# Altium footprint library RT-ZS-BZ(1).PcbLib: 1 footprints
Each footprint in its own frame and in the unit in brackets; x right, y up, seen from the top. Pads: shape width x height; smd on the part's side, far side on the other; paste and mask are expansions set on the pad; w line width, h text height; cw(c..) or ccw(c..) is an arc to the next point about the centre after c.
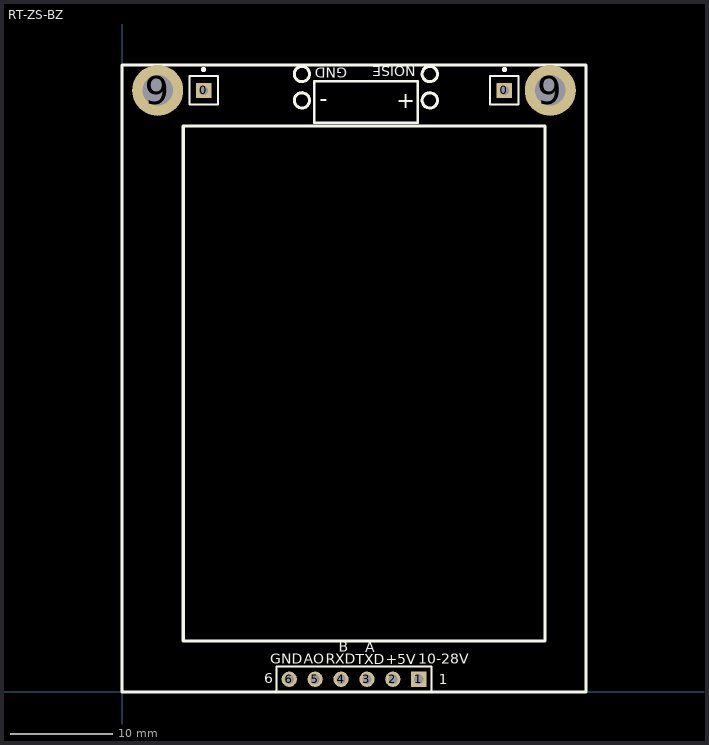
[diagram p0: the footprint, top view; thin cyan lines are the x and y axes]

## RT-ZS-BZ [mm]
pads (10):
  rect 1.5x1.5 hole 0.9: 0(8,59) 0(37.5,59) 1(29.1,1.25)
  round 1.5 hole 0.9: 2(26.56,1.25) 3(24.02,1.25) 4(21.48,1.25) 5(18.94,1.25) 6(16.4,1.25)
  round 5 hole 3: 9(3.5,59) 9(42,59)
Top Overlay:
  circle w0.25: c37.5,61.05 r0.125
  circle w0.25: c8,61.05 r0.125
  circle w0.3: c30.185,58.023 r0.75
  circle w0.3: c30.185,60.605 r0.75
  circle w0.3: c17.642,60.605 r0.75
  circle w0.3: c17.642,58.023 r0.75
  lines w0.2: 6.6,57.6 9.4,57.6 9.4,60.4 6.6,60.4 6.6,57.6 ; 15.13,-0.02 30.37,-0.02 30.37,2.52 15.13,2.52 15.13,-0.02 ; 36.1,57.6 38.9,57.6 38.9,60.4 36.1,60.4 36.1,57.6
  lines w0.254: 18.846,55.833 18.846,59.897 29.006,59.897 29.006,55.833 18.846,55.833
  lines w0.3: 0,0 45.5,0 45.5,61.5 0,61.5 0,0 ; 6,5 41.5,5 41.5,55.5 6,55.5 6,5
  text "6" at 13.965,0.843 h1
  text "1" at 31.04,0.738 h1
  text "AO" at 17.813,2.793 h1
  text "RXD" at 19.973,2.793 h1
  text "TXD" at 22.925,2.74 h1
  text "B" at 21.238,3.952 h1
  text "A" at 23.873,3.9 h1
  text "+5V" at 25.876,2.74 h1
  text "10-28V" at 29.038,2.793 h1
  text "GND" at 22.081,61.237 h1
  text "GND" at 14.545,2.793 h1
  text "NOISE" at 28.827,61.396 h1
  text "+" at 28.774,58.602 h1.6
  text "-" at 20.184,58.655 h1.6
Bottom Overlay:
  lines w0.3: 11.208,17.707 11.208,21.344 ; 16.208,17.76 16.208,21.396 16.208,25.033 21.155,25.033 ; 21.208,17.707 21.208,21.344 21.208,24.98 26.139,24.98 26.139,21.396 ; 22.947,25.085 23,25.033 ; 26.208,17.707 26.208,21.344 ; 31.208,17.707 31.208,21.344 ; 6.208,17.655 6.208,21.344 41.208,21.344 41.208,17.655 6.208,17.655
  lines w0.4: 21.185,14.809 22.661,16.284 ; 22.661,2.74 22.661,16.284 ; 24.137,14.809 22.714,16.232 22.661,16.232 22.661,16.284
  text "1" at 36.205,16.073 h1
  text "1" at 31.357,0.738 h1
  text "AO" at 14.809,18.708 h1.5
  text "B" at 19.235,22.503 h1.5
  text "RXD" at 20.711,18.708 h1.5
  text "A" at 24.242,22.503 h1.5
  text "TXD" at 25.77,18.708 h1.5
  text "+5V" at 30.671,18.708 h1.5
  text "10-28V" at 40.052,18.708 h1.5
  text "6" at 14.598,0.896 h1
  text "GND" at 10.645,18.708 h1.5
  text "6" at 8.432,16.021 h1
3D body: height 1.6, standoff 0, extent 0,0 45.593,61.468
3D body: height 4.01, standoff 0, extent 5.969,4.953 41.529,55.499
3D body: height 3.61, standoff 0, extent 15.113,0 30.353,2.54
